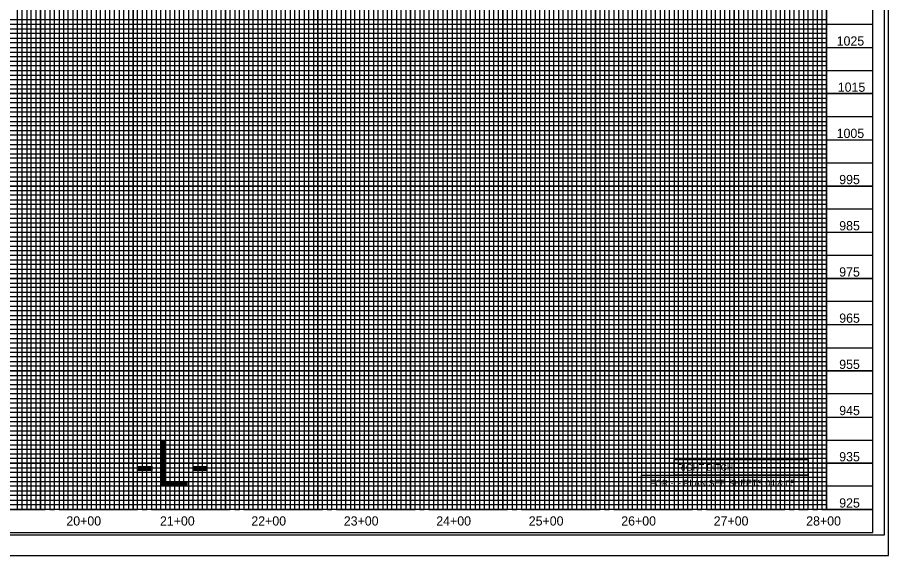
# Model space of a CAD drawing. Extents: x 1260839 to 1262605, y 747346 to 748446.
# Drawn here: x 1261581 to 1262523, y 747346 to 747928 of the extents above; entities that cross this region are included whole.
import ezdxf

# ---------------------------------------------------------------- set-up
doc = ezdxf.new("R2010")
doc.units = 0
for name, color, linetype in [('Pattern 1', 7, 'Continuous'), ('Pattern 2', 7, 'Continuous'), ('Prop Approach Slab', 7, 'Continuous'), ('Prop Drainage Structure Bridge Opening', 7, 'Continuous'), ('Prop Erosion Rip Rap Single Stone CELL', 7, 'Continuous'), ('Prop Grid Mask', 7, 'Continuous'), ('Prop Horizontal Alignment Curve and Spiral Data', 7, 'Continuous'), ('Prop Paved Shoulder', 7, 'Continuous'), ('Prop PFL Text', 7, 'Continuous'), ('Prop Terminator CELL', 7, 'Continuous'), ('Prop Vertical Profile Strip Grade', 7, 'Continuous'), ('Prop VPI Label', 7, 'Continuous'), ('Sheet Border Standard 30in CELL', 7, 'Continuous'), ('Sheet Profile Grid Middle CELL', 7, 'Continuous'), ('Sheet Sticker Exception Certification CELL', 7, 'Continuous')]:
    doc.layers.add(name, color=color, linetype=linetype)

msp = doc.modelspace()

# ---------------------------------------------------------------- linework, layer by layer
at = {"layer": 'Pattern 1'}
for points in [[(1261555.75, 747395.74), (1261605.75, 747395.74), (1261605.75, 748420.74)], [(1261655.75, 748420.74), (1261655.75, 747395.74), (1261705.75, 747395.74), (1261705.75, 748420.74)], [(1261755.75, 748420.74), (1261755.75, 747395.74), (1261805.75, 747395.74), (1261805.75, 748420.74)], [(1261855.75, 748420.74), (1261855.75, 747395.74), (1261905.75, 747395.74), (1261905.75, 748420.74)], [(1261955.75, 748420.74), (1261955.75, 747395.74), (1262005.75, 747395.74), (1262005.75, 748420.74)], [(1262055.75, 748420.74), (1262055.75, 747395.74), (1262105.75, 747395.74), (1262105.75, 748420.74)], [(1262155.75, 748420.74), (1262155.75, 747395.74), (1262205.75, 747395.74), (1262205.75, 748370.74)], [(1262255.75, 748370.74), (1262255.75, 747395.74), (1262305.75, 747395.74), (1262305.75, 748370.74)], [(1262355.75, 748259.69), (1262355.75, 747395.74), (1262405.75, 747395.74), (1262405.75, 748259.69)], [(1262455.75, 748259.69), (1262455.75, 747395.74), (1262505.75, 747395.74)], [(1262505.75, 747845.74), (1261005.75, 747845.74), (1261005.75, 747895.74), (1262505.75, 747895.74)], [(1262505.75, 747745.74), (1261005.75, 747745.74), (1261005.75, 747795.74), (1262505.75, 747795.74)], [(1262505.75, 747645.74), (1261005.75, 747645.74), (1261005.75, 747695.74), (1262505.75, 747695.74)], [(1262505.75, 747545.74), (1261005.75, 747545.74), (1261005.75, 747595.74), (1262505.75, 747595.74)], [(1262505.75, 747445.74), (1261005.75, 747445.74), (1261005.75, 747495.74), (1262505.75, 747495.74)]]:
    msp.add_lwpolyline(points, dxfattribs=at)
at = {"layer": 'Pattern 2'}
for points in [[(1261530.75, 747395.74), (1261580.75, 747395.74), (1261580.75, 748420.74)], [(1261630.75, 748420.74), (1261630.75, 747395.74), (1261680.75, 747395.74), (1261680.75, 748420.74)], [(1261730.75, 748420.74), (1261730.75, 747395.74), (1261780.75, 747395.74), (1261780.75, 748420.74)], [(1261830.75, 748420.74), (1261830.75, 747395.74), (1261880.75, 747395.74), (1261880.75, 748420.74)], [(1261930.75, 748420.74), (1261930.75, 747395.74), (1261980.75, 747395.74), (1261980.75, 748420.74)], [(1262030.75, 748420.74), (1262030.75, 747395.74), (1262080.75, 747395.74), (1262080.75, 748420.74)], [(1262130.75, 748420.74), (1262130.75, 747395.74), (1262180.75, 747395.74), (1262180.75, 748420.74)], [(1262230.75, 748370.74), (1262230.75, 747395.74), (1262280.75, 747395.74), (1262280.75, 748370.74)], [(1262330.75, 748259.69), (1262330.75, 747395.74), (1262380.75, 747395.74), (1262380.75, 748259.69)], [(1262430.75, 748259.69), (1262430.75, 747395.74)], [(1262505.75, 747920.74), (1261005.75, 747920.74), (1261005.75, 747870.74), (1262505.75, 747870.74)], [(1262505.75, 747820.74), (1261005.75, 747820.74), (1261005.75, 747770.74), (1262505.75, 747770.74)], [(1262505.75, 747720.74), (1261005.75, 747720.74), (1261005.75, 747670.74), (1262505.75, 747670.74)], [(1262505.75, 747620.74), (1261005.75, 747620.74), (1261005.75, 747570.74), (1262505.75, 747570.74)], [(1262505.75, 747520.74), (1261005.75, 747520.74), (1261005.75, 747470.74), (1262505.75, 747470.74)], [(1262505.75, 747420.74), (1261005.75, 747420.74)]]:
    msp.add_lwpolyline(points, dxfattribs=at)
at = {"layer": 'Prop Approach Slab'}
msp.add_line((1262357.4, 747441.24), (1262430.39, 747441.24), dxfattribs=at)
at = {"layer": 'Prop Drainage Structure Bridge Opening'}
msp.add_line((1260838.75, 747345.74), (1262522.75, 747345.74), dxfattribs=at)
at = {"layer": 'Prop Erosion Rip Rap Single Stone CELL'}
msp.add_lwpolyline([(1262290.75, 747449.74), (1262435.75, 747449.74), (1262435.75, 747432.74), (1262290.75, 747432.74)], close=True, dxfattribs=at)
at = {"layer": 'Prop Grid Mask'}
msp.add_lwpolyline([(1262455.75, 748259.69), (1262455.75, 747395.74), (1261055.75, 747395.74), (1261055.75, 748420.74), (1262305.7, 748420.74), (1262305.7, 748259.69)], close=True, dxfattribs=at)
at = {"layer": 'Prop Paved Shoulder'}
msp.add_line((1262505.75, 747395.74), (1261005.75, 747395.74), dxfattribs=at)
msp.add_lwpolyline([(1262505.75, 748420.74), (1261005.75, 748420.74), (1261005.75, 747370.74), (1262505.75, 747370.74)], close=True, dxfattribs=at)
at = {"layer": 'Prop PFL Text'}
for p, q in [((1261605.75, 748420.74), (1261605.75, 747395.74)), ((1261655.75, 748420.74), (1261655.75, 747395.74)), ((1261705.75, 748420.74), (1261705.75, 747395.74)), ((1261755.75, 748420.74), (1261755.75, 747395.74)), ((1261805.75, 748420.74), (1261805.75, 747395.74)), ((1261855.75, 748420.74), (1261855.75, 747395.74)), ((1261905.75, 748420.74), (1261905.75, 747395.74)), ((1261955.75, 748420.74), (1261955.75, 747395.74)), ((1262005.75, 748420.74), (1262005.75, 747395.74)), ((1262055.75, 748420.74), (1262055.75, 747395.74)), ((1262105.75, 748420.74), (1262105.75, 747395.74)), ((1262155.75, 748420.74), (1262155.75, 747395.74)), ((1262205.75, 748420.74), (1262205.75, 747395.74)), ((1262255.75, 748370.74), (1262255.75, 747395.74)), ((1262305.75, 747395.74), (1262305.75, 748283.19)), ((1262355.75, 747395.74), (1262355.75, 748259.69)), ((1262405.75, 747395.74), (1262405.75, 748259.69)), ((1262455.75, 747395.74), (1262455.75, 748259.69)), ((1261005.75, 747895.74), (1262505.75, 747895.74)), ((1261005.75, 747845.74), (1262505.75, 747845.74)), ((1261005.75, 747795.74), (1262505.75, 747795.74)), ((1261005.75, 747745.74), (1262505.75, 747745.74)), ((1261005.75, 747695.74), (1262505.75, 747695.74)), ((1261005.75, 747645.74), (1262505.75, 747645.74)), ((1261005.75, 747595.74), (1262505.75, 747595.74)), ((1261005.75, 747545.74), (1262505.75, 747545.74)), ((1261005.75, 747495.74), (1262505.75, 747495.74)), ((1261005.75, 747445.74), (1262505.75, 747445.74))]:
    msp.add_line(p, q, dxfattribs=at)
at = {"layer": 'Prop Terminator CELL'}
msp.add_lwpolyline([(1262518.25, 748423.29), (1260851.75, 748423.29), (1260851.75, 747368.19), (1262518.25, 747368.19)], close=True, dxfattribs=at)
at = {"layer": 'Prop VPI Label'}
msp.add_lwpolyline([(1262522.75, 748445.74), (1260838.75, 748445.74), (1260838.75, 747345.74), (1262522.75, 747345.74)], close=True, dxfattribs=at)
at = {"layer": 'Sheet Profile Grid Middle CELL'}
msp.add_lwpolyline([(1262255.75, 747432.74), (1262435.75, 747432.74), (1262435.75, 747415.74), (1262255.75, 747415.74)], close=True, dxfattribs=at)
at = {"layer": 'Sheet Sticker Exception Certification CELL'}
for points in [[(1261585.75, 747395.74), (1261585.75, 748420.74)], [(1261590.75, 748420.74), (1261590.75, 747395.74), (1261595.75, 747395.74), (1261595.75, 748420.74)], [(1261600.75, 748420.74), (1261600.75, 747395.74), (1261610.75, 747395.74), (1261610.75, 748420.74)], [(1261615.75, 748420.74), (1261615.75, 747395.74), (1261615.75, 747395.74), (1261620.75, 747395.74), (1261620.75, 748420.74)], [(1261625.75, 748420.74), (1261625.75, 747395.74), (1261635.75, 747395.74), (1261635.75, 748420.74)], [(1261640.75, 748420.74), (1261640.75, 747395.74), (1261645.75, 747395.74), (1261645.75, 748420.74)], [(1261650.75, 748420.74), (1261650.75, 747395.74), (1261660.75, 747395.74), (1261660.75, 748420.74)], [(1261665.75, 748420.74), (1261665.75, 747395.74), (1261670.75, 747395.74), (1261670.75, 748420.74)], [(1261675.75, 748420.74), (1261675.75, 747395.74), (1261685.75, 747395.74), (1261685.75, 748420.74)], [(1261690.75, 748420.74), (1261690.75, 747395.74), (1261695.75, 747395.74), (1261695.75, 748420.74)], [(1261700.75, 748420.74), (1261700.75, 747395.74), (1261710.75, 747395.74), (1261710.75, 748420.74)], [(1261715.75, 748420.74), (1261715.75, 747395.74), (1261720.75, 747395.74), (1261720.75, 748420.74)], [(1261725.75, 748420.74), (1261725.75, 747395.74), (1261735.75, 747395.74), (1261735.75, 748420.74)], [(1261740.75, 748420.74), (1261740.75, 747395.74), (1261745.75, 747395.74), (1261745.75, 748420.74)], [(1261750.75, 748420.74), (1261750.75, 747395.74), (1261760.75, 747395.74), (1261760.75, 748420.74)], [(1261765.75, 748420.74), (1261765.75, 747395.74)], [(1261765.75, 747395.74), (1261770.75, 747395.74), (1261770.75, 748420.14)], [(1261775.75, 748420.14), (1261775.75, 747395.74), (1261785.75, 747395.74), (1261785.75, 748420.74)], [(1261790.75, 748420.74), (1261790.75, 747395.74), (1261795.75, 747395.74), (1261795.75, 748420.74)], [(1261800.75, 748420.74), (1261800.75, 747395.74), (1261810.75, 747395.74), (1261810.75, 748420.74)], [(1261815.75, 748420.74), (1261815.75, 747395.74), (1261820.75, 747395.74), (1261820.75, 748420.74)], [(1261825.75, 748420.74), (1261825.75, 747395.74), (1261835.75, 747395.74), (1261835.75, 748420.74)], [(1261840.75, 748420.74), (1261840.75, 747395.74), (1261845.75, 747395.74), (1261845.75, 748420.74)], [(1261850.75, 748420.74), (1261850.75, 747395.74), (1261860.75, 747395.74), (1261860.75, 748420.74)], [(1261865.75, 748420.74), (1261865.75, 747395.74), (1261870.75, 747395.74), (1261870.75, 748420.74)], [(1261875.75, 748420.74), (1261875.75, 747395.74), (1261885.75, 747395.74), (1261885.75, 748420.74)], [(1261890.75, 748420.74), (1261890.75, 747395.74), (1261895.75, 747395.74), (1261895.75, 748420.74)], [(1261900.75, 748420.74), (1261900.75, 747395.74), (1261910.75, 747395.74), (1261910.75, 748420.74)], [(1261915.75, 748420.74), (1261915.75, 747395.74), (1261920.75, 747395.74), (1261920.75, 748420.74)], [(1261925.75, 748420.74), (1261925.75, 747395.74), (1261935.75, 747395.74), (1261935.75, 748420.74)], [(1261940.75, 748420.74), (1261940.75, 747395.74), (1261945.75, 747395.74), (1261945.75, 748420.74)], [(1261950.75, 748420.74), (1261950.75, 747395.74), (1261960.75, 747395.74), (1261960.75, 748420.74)], [(1261965.75, 748420.74), (1261965.75, 747395.74), (1261970.75, 747395.74), (1261970.75, 748420.74)], [(1261975.75, 748420.74), (1261975.75, 747395.74), (1261985.75, 747395.74), (1261985.75, 748420.74)], [(1261990.75, 748420.74), (1261990.75, 747395.74), (1261995.75, 747395.74), (1261995.75, 748420.74)], [(1262000.75, 748420.74), (1262000.75, 747395.74), (1262010.75, 747395.74), (1262010.75, 748420.74)], [(1262015.75, 748420.74), (1262015.75, 747395.74), (1262020.75, 747395.74), (1262020.75, 748420.74)], [(1262025.75, 748420.74), (1262025.75, 747395.74), (1262035.75, 747395.74), (1262035.75, 748420.74)], [(1262040.75, 748420.74), (1262040.75, 747395.74), (1262045.75, 747395.74), (1262045.75, 748420.74)], [(1262050.75, 748420.74), (1262050.75, 747395.74), (1262060.75, 747395.74), (1262060.75, 748420.74)], [(1262065.75, 748420.74), (1262065.75, 747395.74), (1262070.75, 747395.74), (1262070.75, 748420.74)], [(1262075.75, 748420.74), (1262075.75, 747395.74)], [(1262075.75, 747395.74), (1262085.75, 747395.74), (1262085.75, 748420.74)], [(1262090.75, 748420.74), (1262090.75, 747395.74), (1262095.75, 747395.74), (1262095.75, 748420.74)], [(1262100.75, 748420.74), (1262100.75, 747395.74), (1262110.75, 747395.74), (1262110.75, 748420.74)], [(1262115.75, 748420.74), (1262115.75, 747395.74), (1262120.75, 747395.74), (1262120.75, 748420.74)], [(1262125.75, 748420.74), (1262125.75, 747395.74), (1262135.75, 747395.74), (1262135.75, 748420.74)], [(1262140.75, 748420.74), (1262140.75, 747395.74), (1262145.75, 747395.74), (1262145.75, 748420.74)], [(1262150.75, 748420.74), (1262150.75, 747395.74), (1262160.75, 747395.74), (1262160.75, 748420.74)], [(1262165.75, 748420.74), (1262165.75, 747395.74), (1262170.75, 747395.74), (1262170.75, 748420.74)], [(1262175.75, 748420.74), (1262175.75, 747395.74), (1262185.75, 747395.74), (1262185.75, 748420.74)], [(1262190.75, 748420.74), (1262190.75, 747395.74), (1262195.75, 747395.74), (1262195.75, 748420.74)], [(1262200.75, 748420.74), (1262200.75, 747395.74), (1262210.75, 747395.74), (1262210.75, 748370.74)], [(1262215.75, 748370.74), (1262215.75, 747395.74), (1262220.75, 747395.74), (1262220.75, 748370.74)], [(1262225.75, 748370.74), (1262225.75, 747395.74), (1262235.75, 747395.74), (1262235.75, 748370.74)], [(1262240.75, 748370.74), (1262240.75, 747395.74), (1262245.75, 747395.74), (1262245.75, 748370.74)], [(1262250.75, 748370.74), (1262250.75, 747395.74), (1262260.75, 747395.74), (1262260.75, 748370.74)], [(1262265.75, 748370.74), (1262265.75, 747395.74), (1262270.75, 747395.74), (1262270.75, 748370.74)], [(1262275.75, 748370.74), (1262275.75, 747395.74), (1262285.75, 747395.74), (1262285.75, 748370.74)], [(1262290.75, 748370.74), (1262290.75, 747395.74), (1262295.75, 747395.74), (1262295.75, 748370.74)], [(1262300.75, 748370.74), (1262300.75, 747395.74), (1262310.75, 747395.74), (1262310.75, 748259.69)], [(1262315.75, 748259.69), (1262315.75, 747395.74), (1262320.75, 747395.74), (1262320.75, 748259.69)], [(1262325.75, 748259.69), (1262325.75, 747395.74), (1262335.75, 747395.74), (1262335.75, 748259.69)], [(1262340.75, 748259.69), (1262340.75, 747395.74), (1262345.75, 747395.74), (1262345.75, 748259.69)], [(1262350.75, 748259.69), (1262350.75, 747395.74), (1262360.75, 747395.74), (1262360.75, 748259.69)], [(1262365.75, 748259.69), (1262365.75, 747395.74), (1262370.75, 747395.74), (1262370.75, 748259.69)], [(1262375.75, 748259.69), (1262375.75, 747395.74), (1262385.75, 747395.74), (1262385.75, 748259.69)], [(1262390.75, 748259.69), (1262390.75, 747395.74)], [(1262390.75, 747395.74), (1262395.75, 747395.74), (1262395.75, 748259.69)], [(1262400.75, 748259.69), (1262400.75, 747395.74), (1262410.75, 747395.74), (1262410.75, 748259.69)], [(1262415.75, 748259.69), (1262415.75, 747395.74), (1262420.75, 747395.74), (1262420.75, 748259.69)], [(1262425.75, 748259.69), (1262425.75, 747395.74), (1262435.75, 747395.74), (1262435.75, 748259.69)], [(1262440.75, 748259.69), (1262440.75, 747395.74), (1262445.75, 747395.74), (1262445.75, 748259.69)], [(1262450.75, 748259.69), (1262450.75, 747395.74), (1262460.75, 747395.74)], [(1262455.75, 747925.74), (1261055.75, 747925.74), (1261055.75, 747915.74), (1262455.75, 747915.74)], [(1262455.75, 747910.74), (1261055.75, 747910.74), (1261055.75, 747905.74), (1262455.75, 747905.74)], [(1262455.75, 747900.74), (1261055.75, 747900.74)], [(1261055.75, 747890.74), (1262455.75, 747890.74)], [(1262455.75, 747885.74), (1261055.75, 747885.74), (1261055.75, 747880.74), (1262455.75, 747880.74)], [(1262455.75, 747875.74), (1261055.75, 747875.74), (1261055.75, 747865.74), (1262455.75, 747865.74)], [(1262455.75, 747860.74), (1261055.75, 747860.74), (1261055.75, 747855.74), (1262455.75, 747855.74)], [(1262455.75, 747850.74), (1261055.75, 747850.74), (1261055.75, 747840.74), (1262455.75, 747840.74)], [(1262455.75, 747835.74), (1261055.75, 747835.74), (1261055.75, 747830.74), (1262455.75, 747830.74)], [(1262455.75, 747825.74), (1261055.75, 747825.74), (1261055.75, 747815.74), (1262455.75, 747815.74)], [(1262455.75, 747810.74), (1261055.75, 747810.74), (1261055.75, 747805.74), (1262455.75, 747805.74)], [(1262455.75, 747800.74), (1261055.75, 747800.74), (1261055.75, 747790.74), (1262455.75, 747790.74)], [(1262455.75, 747785.74), (1261055.75, 747785.74), (1261055.75, 747780.74), (1262455.75, 747780.74)], [(1262455.75, 747775.74), (1261055.75, 747775.74), (1261055.75, 747765.74), (1262455.75, 747765.74)], [(1262455.75, 747760.74), (1261055.75, 747760.74), (1261055.75, 747755.74), (1262455.75, 747755.74)], [(1262455.75, 747750.74), (1261055.75, 747750.74), (1261055.75, 747740.74), (1262455.75, 747740.74)], [(1262455.75, 747735.74), (1261055.75, 747735.74), (1261055.75, 747730.74), (1262455.75, 747730.74)], [(1262455.75, 747725.74), (1261055.75, 747725.74), (1261055.75, 747715.74), (1262455.75, 747715.74)], [(1262455.75, 747710.74), (1261055.75, 747710.74), (1261055.75, 747705.74), (1262455.75, 747705.74)], [(1262455.75, 747700.74), (1261055.75, 747700.74), (1261055.75, 747690.74), (1262455.75, 747690.74)], [(1262455.75, 747685.74), (1261055.75, 747685.74), (1261055.75, 747680.74), (1262455.75, 747680.74)], [(1262455.75, 747675.74), (1261055.75, 747675.74), (1261055.75, 747665.74), (1262455.75, 747665.74)], [(1262455.75, 747660.74), (1261055.75, 747660.74), (1261055.75, 747655.74), (1262455.75, 747655.74)], [(1262455.75, 747650.74), (1261055.75, 747650.74), (1261055.75, 747640.74), (1262455.75, 747640.74)], [(1262455.75, 747635.74), (1261055.75, 747635.74), (1261055.75, 747630.74), (1262455.75, 747630.74)], [(1262455.75, 747625.74), (1261055.75, 747625.74), (1261055.75, 747615.74), (1262455.75, 747615.74)], [(1262455.75, 747610.74), (1261055.75, 747610.74), (1261055.75, 747605.74), (1262455.75, 747605.74)], [(1262455.75, 747600.74), (1261055.75, 747600.74)], [(1261055.75, 747590.74), (1262455.75, 747590.74)], [(1262455.75, 747585.74), (1261055.75, 747585.74), (1261055.75, 747580.74), (1262455.75, 747580.74)], [(1262455.75, 747575.74), (1261055.75, 747575.74)], [(1261055.75, 747565.74), (1262455.75, 747565.74)], [(1262455.75, 747560.74), (1261055.75, 747560.74), (1261055.75, 747555.74), (1262455.75, 747555.74)], [(1262455.75, 747550.74), (1261055.75, 747550.74), (1261055.75, 747540.74), (1262455.75, 747540.74)], [(1262455.75, 747535.74), (1261055.75, 747535.74), (1261055.75, 747530.74), (1262455.75, 747530.74)], [(1262455.75, 747525.74), (1261055.75, 747525.74), (1261055.75, 747515.74), (1262455.75, 747515.74)], [(1262455.75, 747510.74), (1261055.75, 747510.74), (1261055.75, 747505.74), (1262455.75, 747505.74)], [(1262455.75, 747500.74), (1261055.75, 747500.74), (1261055.75, 747490.74), (1262455.75, 747490.74)], [(1262455.75, 747485.74), (1261055.75, 747485.74), (1261055.75, 747480.74), (1262455.75, 747480.74)], [(1262455.75, 747475.74), (1261055.75, 747475.74), (1261055.75, 747465.74), (1262455.75, 747465.74)], [(1262455.75, 747460.74), (1261055.75, 747460.74), (1261055.75, 747455.74), (1262455.75, 747455.74)], [(1262455.75, 747450.74), (1261055.75, 747450.74), (1261055.75, 747440.74), (1262455.75, 747440.74)], [(1262455.75, 747435.74), (1261055.75, 747435.74), (1261055.75, 747430.74), (1262455.75, 747430.74)], [(1262455.75, 747425.74), (1261055.75, 747425.74), (1261055.75, 747415.74), (1262455.75, 747415.74)], [(1262455.75, 747410.74), (1261055.75, 747410.74), (1261055.75, 747405.74), (1262455.75, 747405.74)], [(1262455.75, 747400.74), (1261055.75, 747400.74)]]:
    msp.add_lwpolyline(points, dxfattribs=at)

# ---------------------------------------------------------------- texts
at = {"layer": 'Prop Erosion Rip Rap Single Stone CELL'}
for s, p in [('RIGHT DITCH', (1262294.28, 747437.73)), ('FOR -L- PLAN SEE SHEETS 04 & 05', (1262264.66, 747420.74))]:
    msp.add_text(s, height=7, dxfattribs=at).set_placement(p)
at = {"layer": 'Prop Horizontal Alignment Curve and Spiral Data'}
for s, p in [('20+00', (1261633.69, 747378.24)), ('21+00', (1261734.88, 747378.24)), ('22+00', (1261833.69, 747378.24)), ('23+00', (1261933.69, 747378.24)), ('24+00', (1262033.69, 747378.24)), ('25+00', (1262133.69, 747378.24)), ('26+00', (1262233.69, 747378.24)), ('27+00', (1262333.69, 747378.24)), ('28+00', (1262433.69, 747378.24))]:
    msp.add_text(s, height=10, dxfattribs=at).set_placement(p)
at = {"layer": 'Prop Vertical Profile Strip Grade'}
for s, p in [('1025', (1262466.63, 747897.74)), ('1015', (1262467.83, 747847.74)), ('1005', (1262466.63, 747797.74)), ('995', (1262469.39, 747747.74)), ('985', (1262469.39, 747697.74)), ('975', (1262469.39, 747647.74)), ('965', (1262469.39, 747597.74)), ('955', (1262469.39, 747547.74)), ('945', (1262469.39, 747497.74)), ('935', (1262469.39, 747447.74)), ('925', (1262469.39, 747397.74))]:
    msp.add_text(s, height=10, dxfattribs=at).set_placement(p)
at = {"layer": 'Sheet Border Standard 30in CELL'}
msp.add_text('-L-', height=50, dxfattribs=at).set_placement((1261707.65, 747420.74))

doc.saveas('drawing.dxf')
